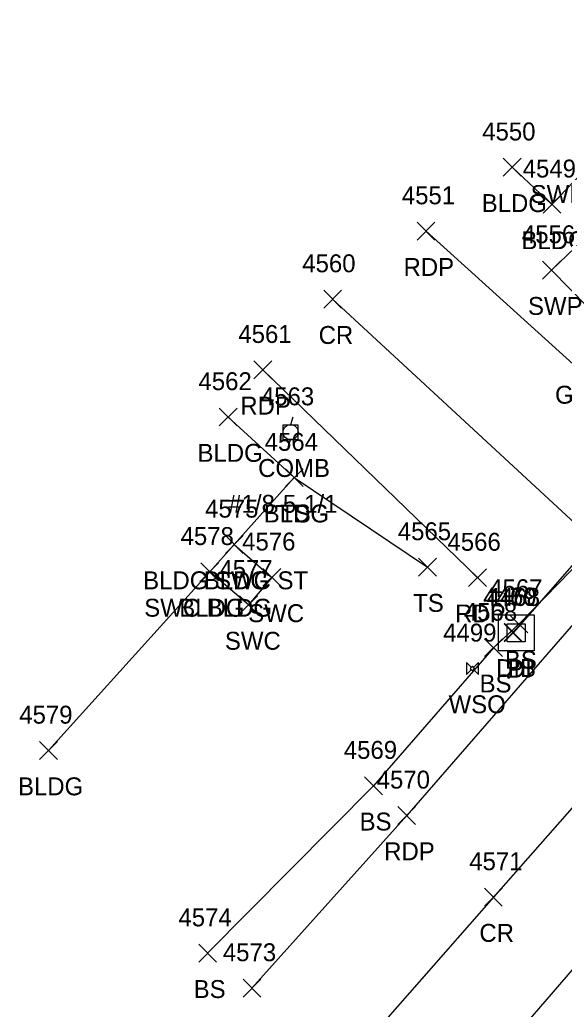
# Model space of a CAD drawing. Extents: x 1653135 to 1655489, y 602711 to 605684.
# Drawn here: x 1653134.6 to 1653195.4, y 604809.6 to 604920.1 of the extents above; entities that cross this region are included whole.
import ezdxf

# ---------------------------------------------------------------- set-up
doc = ezdxf.new("R2010")
doc.units = 0
for name, color, linetype in [('D_A', 7, 'Continuous'), ('D_I', 7, 'Continuous'), ('D_TIC', 7, 'Continuous'), ('DCP', 7, 'Continuous'), ('DS', 7, 'Continuous'), ('L_A', 7, 'Continuous'), ('L_I', 7, 'Continuous'), ('L_TIC', 7, 'Continuous'), ('LBC', 7, 'Continuous'), ('LELB', 7, 'Continuous'), ('P_A', 7, 'Continuous'), ('P_I', 7, 'Continuous'), ('P_TIC', 7, 'Continuous'), ('PET', 7, 'Continuous'), ('PRC', 7, 'Continuous'), ('R_A', 7, 'Continuous'), ('R_I', 7, 'Continuous'), ('R_TIC', 7, 'Continuous'), ('RSW', 7, 'Continuous'), ('S_C', 7, 'Continuous'), ('U_A', 7, 'Continuous'), ('U_C', 7, 'Continuous'), ('U_I', 7, 'Continuous'), ('UP', 7, 'Continuous'), ('UWV', 7, 'Continuous')]:
    doc.layers.add(name, color=color, linetype=linetype)

msp = doc.modelspace()

# ---------------------------------------------------------------- linework, layer by layer
at = {"layer": 'D_TIC'}
for points in [[(1653188.69, 604850.7), (1653190.69, 604852.7)], [(1653190.69, 604850.7), (1653188.69, 604852.7)], [(1653188.69, 604850.7), (1653190.69, 604852.7)], [(1653190.69, 604850.7), (1653188.69, 604852.7)], [(1653188.69, 604850.65), (1653190.69, 604852.65)], [(1653190.69, 604850.65), (1653188.69, 604852.65)], [(1653188.69, 604850.65), (1653190.69, 604852.65)], [(1653190.69, 604850.65), (1653188.69, 604852.65)]]:
    msp.add_lwpolyline(points, dxfattribs=at)
at = {"layer": 'DCP'}
msp.add_lwpolyline([(1653210.41, 604875.27), (1653189.69, 604851.65)], dxfattribs=at)
at = {"layer": 'DS'}
for p, q in [((1653188.05, 604853.64), (1653192.05, 604853.64)), ((1653188.05, 604849.64), (1653188.05, 604853.64)), ((1653189.05, 604850.64), (1653189.05, 604852.64)), ((1653189.05, 604852.64), (1653191.05, 604852.64)), ((1653191.05, 604852.64), (1653191.05, 604850.64)), ((1653192.05, 604853.64), (1653192.05, 604849.64)), ((1653190.06, 604851.64), (1653190.06, 604851.64)), ((1653190.06, 604851.64), (1653190.06, 604851.64)), ((1653191.05, 604850.64), (1653189.05, 604850.64)), ((1653192.05, 604849.64), (1653188.05, 604849.64))]:
    msp.add_line(p, q, dxfattribs=at)
at = {"layer": 'L_TIC'}
for points in [[(1653188.6, 604902.61), (1653190.6, 604904.61)], [(1653190.6, 604902.61), (1653188.6, 604904.61)], [(1653188.6, 604902.61), (1653190.6, 604904.61)], [(1653190.6, 604902.61), (1653188.6, 604904.61)], [(1653193.04, 604898.47), (1653195.04, 604900.47)], [(1653195.04, 604898.47), (1653193.04, 604900.47)], [(1653193.04, 604898.47), (1653195.04, 604900.47)], [(1653195.04, 604898.47), (1653193.04, 604900.47)], [(1653156.86, 604874.73), (1653158.86, 604876.73)], [(1653158.86, 604874.73), (1653156.86, 604876.73)], [(1653156.86, 604874.73), (1653158.86, 604876.73)], [(1653158.86, 604874.73), (1653156.86, 604876.73)], [(1653164.26, 604867.96), (1653166.26, 604869.96)], [(1653166.26, 604867.96), (1653164.26, 604869.96)], [(1653164.26, 604867.96), (1653166.26, 604869.96)], [(1653166.26, 604867.96), (1653164.26, 604869.96)], [(1653164.26, 604867.96), (1653166.26, 604869.96)], [(1653166.26, 604867.96), (1653164.26, 604869.96)], [(1653164.26, 604867.96), (1653166.26, 604869.96)], [(1653166.26, 604867.96), (1653164.26, 604869.96)], [(1653157.56, 604860.5), (1653159.56, 604862.5)], [(1653159.56, 604860.5), (1653157.56, 604862.5)], [(1653157.56, 604860.5), (1653159.56, 604862.5)], [(1653159.56, 604860.5), (1653157.56, 604862.5)], [(1653154.81, 604857.44), (1653156.81, 604859.44)], [(1653156.81, 604857.44), (1653154.81, 604859.44)], [(1653154.81, 604857.44), (1653156.81, 604859.44)], [(1653156.81, 604857.44), (1653154.81, 604859.44)], [(1653179.13, 604857.98), (1653181.13, 604859.98)], [(1653181.13, 604857.98), (1653179.13, 604859.98)], [(1653179.13, 604857.98), (1653181.13, 604859.98)], [(1653181.13, 604857.98), (1653179.13, 604859.98)], [(1653189.33, 604851.62), (1653191.33, 604853.62)], [(1653191.33, 604851.62), (1653189.33, 604853.62)], [(1653189.33, 604851.62), (1653191.33, 604853.62)], [(1653191.33, 604851.62), (1653189.33, 604853.62)], [(1653186.51, 604848.98), (1653188.51, 604850.98)], [(1653188.51, 604848.98), (1653186.51, 604850.98)], [(1653186.51, 604848.98), (1653188.51, 604850.98)], [(1653188.51, 604848.98), (1653186.51, 604850.98)], [(1653136.8, 604837.5), (1653138.8, 604839.5)], [(1653138.8, 604837.5), (1653136.8, 604839.5)], [(1653136.8, 604837.5), (1653138.8, 604839.5)], [(1653138.8, 604837.5), (1653136.8, 604839.5)], [(1653173.11, 604833.57), (1653175.11, 604835.57)], [(1653175.11, 604833.57), (1653173.11, 604835.57)], [(1653173.11, 604833.57), (1653175.11, 604835.57)], [(1653175.11, 604833.57), (1653173.11, 604835.57)], [(1653154.58, 604814.87), (1653156.58, 604816.87)], [(1653156.58, 604814.87), (1653154.58, 604816.87)], [(1653154.58, 604814.87), (1653156.58, 604816.87)], [(1653156.58, 604814.87), (1653154.58, 604816.87)]]:
    msp.add_lwpolyline(points, dxfattribs=at)
at = {"layer": 'LBC'}
for points in [[(1653219.99, 604933.48), (1653223.22, 604930.63), (1653221.42, 604928.5), (1653212.33, 604918.97), (1653207.68, 604913.99), (1653198.97, 604904.62), (1653194.04, 604899.47), (1653189.6, 604903.61)], [(1653157.86, 604875.73), (1653165.26, 604868.96), (1653158.56, 604861.5), (1653155.81, 604858.44), (1653137.8, 604838.5)]]:
    msp.add_lwpolyline(points, dxfattribs=at)
at = {"layer": 'LELB'}
for points in [[(1653208.32, 604875.11), (1653199.08, 604861.57), (1653190.33, 604852.62), (1653187.51, 604849.98), (1653174.11, 604834.57), (1653155.58, 604815.87)], [(1653165.26, 604868.96), (1653180.13, 604858.98)]]:
    msp.add_lwpolyline(points, dxfattribs=at)
at = {"layer": 'P_TIC'}
for points in [[(1653178.97, 604895.48), (1653180.97, 604897.48)], [(1653180.97, 604895.48), (1653178.97, 604897.48)], [(1653178.97, 604895.48), (1653180.97, 604897.48)], [(1653180.97, 604895.48), (1653178.97, 604897.48)], [(1653168.54, 604887.89), (1653170.54, 604889.89)], [(1653170.54, 604887.89), (1653168.54, 604889.89)], [(1653168.54, 604887.89), (1653170.54, 604889.89)], [(1653170.54, 604887.89), (1653168.54, 604889.89)], [(1653160.75, 604880), (1653162.75, 604882)], [(1653162.75, 604880), (1653160.75, 604882)], [(1653160.75, 604880), (1653162.75, 604882)], [(1653162.75, 604880), (1653160.75, 604882)], [(1653184.73, 604856.8), (1653186.73, 604858.8)], [(1653186.73, 604856.8), (1653184.73, 604858.8)], [(1653184.73, 604856.8), (1653186.73, 604858.8)], [(1653186.73, 604856.8), (1653184.73, 604858.8)], [(1653176.81, 604830.25), (1653178.81, 604832.25)], [(1653178.81, 604830.25), (1653176.81, 604832.25)], [(1653176.81, 604830.25), (1653178.81, 604832.25)], [(1653178.81, 604830.25), (1653176.81, 604832.25)], [(1653186.49, 604821.14), (1653188.49, 604823.14)], [(1653188.49, 604821.14), (1653186.49, 604823.14)], [(1653186.49, 604821.14), (1653188.49, 604823.14)], [(1653188.49, 604821.14), (1653186.49, 604823.14)], [(1653159.53, 604810.98), (1653161.53, 604812.98)], [(1653161.53, 604810.98), (1653159.53, 604812.98)], [(1653159.53, 604810.98), (1653161.53, 604812.98)], [(1653161.53, 604810.98), (1653159.53, 604812.98)]]:
    msp.add_lwpolyline(points, dxfattribs=at)
at = {"layer": 'PET'}
for points in [[(1653570.48, 605162.79), (1653545.4, 605152.19), (1653524.6, 605144.34), (1653501.66, 605134.24), (1653492.53, 605129.6), (1653483.22, 605126.16), (1653461.51, 605114.2), (1653431.75, 605097.05), (1653402.44, 605074.2), (1653383.5, 605058.49), (1653369.86, 605045.73), (1653350.11, 605021.59), (1653336.01, 605007.55), (1653322.85, 604993.82), (1653302.17, 604970.77), (1653290.93, 604958.38), (1653272.17, 604938.1), (1653250.65, 604913.14), (1653232.41, 604892.9), (1653208.36, 604866.32), (1653177.81, 604831.25), (1653160.53, 604811.98)], [(1653576.32, 605135.26), (1653553.77, 605126.84), (1653519.05, 605112.42), (1653493.54, 605100.34), (1653468.83, 605088), (1653447.85, 605075.02), (1653427.6, 605061.87), (1653406.78, 605044.61), (1653388.9, 605027.7), (1653366.5, 605004.89), (1653354.58, 604992.02), (1653334.9, 604970.66), (1653318.05, 604952.19), (1653296.49, 604928.19), (1653274.62, 604903.56), (1653244.24, 604868.76), (1653225.75, 604847.7), (1653206.33, 604825.65), (1653179.65, 604794.75)], [(1653179.97, 604896.48), (1653201.88, 604876.69)], [(1653161.75, 604881), (1653185.73, 604857.8)]]:
    msp.add_lwpolyline(points, dxfattribs=at)
at = {"layer": 'PRC'}
for points in [[(1653576.36, 605149.52), (1653550.32, 605139.02), (1653518.72, 605125.67), (1653498.02, 605116.67), (1653468.04, 605101.49), (1653440.12, 605084.85), (1653411.97, 605063.45), (1653392.18, 605045.92), (1653380.93, 605035.31), (1653360.25, 605013.97), (1653332.49, 604984.79), (1653311.15, 604961.54), (1653300.12, 604949.23), (1653281.61, 604928.68), (1653260.96, 604905.28), (1653242.09, 604884.43), (1653216.57, 604855.12), (1653187.49, 604822.14), (1653170.08, 604802.31)], [(1653199.08, 604861.57), (1653169.54, 604888.89)]]:
    msp.add_lwpolyline(points, dxfattribs=at)
at = {"layer": 'R_TIC'}
for points in [[(1653192.99, 604891.13), (1653194.99, 604893.13)], [(1653194.99, 604891.13), (1653192.99, 604893.13)], [(1653192.99, 604891.13), (1653194.99, 604893.13)], [(1653194.99, 604891.13), (1653192.99, 604893.13)], [(1653157.56, 604860.5), (1653159.56, 604862.5)], [(1653159.56, 604860.5), (1653157.56, 604862.5)], [(1653157.56, 604860.5), (1653159.56, 604862.5)], [(1653159.56, 604860.5), (1653157.56, 604862.5)], [(1653154.81, 604857.44), (1653156.81, 604859.44)], [(1653156.81, 604857.44), (1653154.81, 604859.44)], [(1653154.81, 604857.44), (1653156.81, 604859.44)], [(1653156.81, 604857.44), (1653154.81, 604859.44)], [(1653161.75, 604856.83), (1653163.75, 604858.83)], [(1653163.75, 604856.83), (1653161.75, 604858.83)], [(1653161.75, 604856.83), (1653163.75, 604858.83)], [(1653163.75, 604856.83), (1653161.75, 604858.83)], [(1653159.15, 604853.75), (1653161.15, 604855.75)], [(1653161.15, 604853.75), (1653159.15, 604855.75)], [(1653159.15, 604853.75), (1653161.15, 604855.75)], [(1653161.15, 604853.75), (1653159.15, 604855.75)]]:
    msp.add_lwpolyline(points, dxfattribs=at)
at = {"layer": 'RSW'}
for points in [[(1653211.16, 604886.92), (1653204.07, 604892.89), (1653199.17, 604897.08), (1653193.99, 604892.13), (1653204.08, 604881.84)], [(1653158.56, 604861.5), (1653162.75, 604857.83), (1653160.15, 604854.75), (1653155.81, 604858.44)]]:
    msp.add_lwpolyline(points, dxfattribs=at)
at = {"layer": 'UP'}
for p, q in [((1653164, 604873.2), (1653164, 604874.87)), ((1653164, 604874.87), (1653165.67, 604874.87)), ((1653165.09, 604875.7), (1653164.84, 604874.87)), ((1653165.67, 604874.87), (1653165.67, 604873.2)), ((1653164.84, 604874.04), (1653164.84, 604874.04)), ((1653165.67, 604873.2), (1653164, 604873.2)), ((1653164.59, 604872.37), (1653164.84, 604873.2))]:
    msp.add_line(p, q, dxfattribs=at)
msp.add_circle((1653164.84, 604874.04), 0.833, dxfattribs=at)
at = {"layer": 'UWV'}
for p, q in [((1653184.49, 604848.33), (1653185.04, 604847.78)), ((1653185.82, 604848.33), (1653185.27, 604847.78)), ((1653185.04, 604847.54), (1653184.49, 604846.99)), ((1653185.27, 604847.54), (1653185.82, 604846.99))]:
    msp.add_line(p, q, dxfattribs=at)
for points in [[(1653184.49, 604848.33), (1653184.49, 604846.99)], [(1653185.82, 604846.99), (1653185.82, 604848.33)]]:
    msp.add_lwpolyline(points, dxfattribs=at)
msp.add_lwpolyline([(1653185.39, 604847.66), (1653185.16, 604847.9), (1653184.92, 604847.66), (1653185.16, 604847.43)], close=True, dxfattribs=at)

# ---------------------------------------------------------------- texts
at = {"layer": 'D_A'}
for s, p in [('DIB', (1653187.79, 604846.7)), ('DIB', (1653187.79, 604846.7)), ('P', (1653189.07, 604846.65)), ('P', (1653189.07, 604846.65)), ('DI', (1653189.11, 604846.64))]:
    msp.add_text(s, height=2, dxfattribs=at).set_placement(p)
at = {"layer": 'D_I'}
for s, p in [('4470', (1653186.34, 604854.65)), ('4470', (1653186.34, 604854.65)), ('4469', (1653186.37, 604854.7)), ('4469', (1653186.37, 604854.7)), ('4468', (1653186.75, 604854.64))]:
    msp.add_text(s, height=2, dxfattribs=at).set_placement(p)
at = {"layer": 'L_A'}
for s, p in [('BLDG', (1653186.19, 604898.61)), ('BLDG', (1653186.19, 604898.61)), ('BLDG', (1653190.63, 604894.47)), ('BLDG', (1653190.63, 604894.47)), ('BLDG', (1653154.45, 604870.73)), ('BLDG', (1653154.45, 604870.73)), ('BLDG', (1653161.85, 604863.96)), ('BLDG', (1653161.85, 604863.96)), ('TS', (1653163.67, 604863.96)), ('TS', (1653163.67, 604863.96)), ('BLDG', (1653155.15, 604856.5)), ('BLDG', (1653155.15, 604856.5)), ('TS', (1653178.54, 604853.98)), ('TS', (1653178.54, 604853.98)), ('BLDG', (1653152.41, 604853.44)), ('BLDG', (1653152.41, 604853.44)), ('BS', (1653188.78, 604847.62)), ('BS', (1653188.78, 604847.62)), ('BS', (1653185.95, 604844.98)), ('BS', (1653185.95, 604844.98)), ('BLDG', (1653134.4, 604833.5)), ('BLDG', (1653134.4, 604833.5)), ('BS', (1653172.55, 604829.57)), ('BS', (1653172.55, 604829.57)), ('BS', (1653154.02, 604810.87)), ('BS', (1653154.02, 604810.87))]:
    msp.add_text(s, height=2, dxfattribs=at).set_placement(p)
at = {"layer": 'L_I'}
for s, p in [('4550', (1653186.25, 604906.61)), ('4550', (1653186.25, 604906.61)), ('4549', (1653190.77, 604902.47)), ('4549', (1653190.77, 604902.47)), ('4562', (1653154.56, 604878.73)), ('4562', (1653154.56, 604878.73)), ('4564', (1653161.95, 604871.96)), ('4564', (1653161.95, 604871.96)), ('4564', (1653161.95, 604871.96)), ('4564', (1653161.95, 604871.96)), ('4575', (1653155.3, 604864.5)), ('4575', (1653155.3, 604864.5)), ('4565', (1653176.82, 604861.98)), ('4565', (1653176.82, 604861.98)), ('4578', (1653152.56, 604861.44)), ('4578', (1653152.56, 604861.44)), ('4567', (1653187.03, 604855.62)), ('4567', (1653187.03, 604855.62)), ('4568', (1653184.2, 604852.98)), ('4568', (1653184.2, 604852.98)), ('4579', (1653134.54, 604841.5)), ('4579', (1653134.54, 604841.5)), ('4569', (1653170.79, 604837.57)), ('4569', (1653170.79, 604837.57)), ('4574', (1653152.32, 604818.87)), ('4574', (1653152.32, 604818.87))]:
    msp.add_text(s, height=2, dxfattribs=at).set_placement(p)
at = {"layer": 'P_A'}
for s, p in [('RDP', (1653177.46, 604891.48)), ('RDP', (1653177.46, 604891.48)), ('CR', (1653167.98, 604883.89)), ('CR', (1653167.98, 604883.89)), ('RDP', (1653159.23, 604876)), ('RDP', (1653159.23, 604876)), ('RDP', (1653183.22, 604852.8)), ('RDP', (1653183.22, 604852.8)), ('RDP', (1653175.3, 604826.25)), ('RDP', (1653175.3, 604826.25)), ('CR', (1653185.93, 604817.14)), ('CR', (1653185.93, 604817.14))]:
    msp.add_text(s, height=2, dxfattribs=at).set_placement(p)
at = {"layer": 'P_I'}
for s, p in [('4551', (1653177.27, 604899.48)), ('4551', (1653177.27, 604899.48)), ('4560', (1653166.15, 604891.89)), ('4560', (1653166.15, 604891.89)), ('4561', (1653159.01, 604884)), ('4561', (1653159.01, 604884)), ('4566', (1653182.37, 604860.8)), ('4566', (1653182.37, 604860.8)), ('4570', (1653174.46, 604834.25)), ('4570', (1653174.46, 604834.25)), ('4571', (1653184.8, 604825.14)), ('4571', (1653184.8, 604825.14)), ('4573', (1653157.28, 604814.98)), ('4573', (1653157.28, 604814.98))]:
    msp.add_text(s, height=2, dxfattribs=at).set_placement(p)
at = {"layer": 'R_A'}
for s, p in [('SWP BLDG', (1653191.66, 604899.62)), ('SWP BLDG', (1653191.66, 604899.62)), ('SWP', (1653191.36, 604887.13)), ('SWP', (1653191.36, 604887.13)), ('BLDG SWC ST', (1653148.38, 604856.5)), ('BLDG SWC ST', (1653148.38, 604856.5)), ('SWC BLDG', (1653148.5, 604853.44)), ('SWC BLDG', (1653148.5, 604853.44)), ('SWC', (1653160.12, 604852.83)), ('SWC', (1653160.12, 604852.83)), ('SWC', (1653157.51, 604849.75)), ('SWC', (1653157.51, 604849.75))]:
    msp.add_text(s, height=2, dxfattribs=at).set_placement(p)
at = {"layer": 'R_I'}
for s, p in [('4556', (1653190.68, 604895.13)), ('4556', (1653190.68, 604895.13)), ('4575', (1653155.3, 604864.5)), ('4575', (1653155.3, 604864.5)), ('4578', (1653152.56, 604861.44)), ('4578', (1653152.56, 604861.44)), ('4576', (1653159.44, 604860.83)), ('4576', (1653159.44, 604860.83)), ('4577', (1653156.89, 604857.75)), ('4577', (1653156.89, 604857.75))]:
    msp.add_text(s, height=2, dxfattribs=at).set_placement(p)
at = {"layer": 'S_C'}
msp.add_text('GARDEN ST', height=2, dxfattribs=at).set_placement((1653194.38, 604877.22))
at = {"layer": 'U_A'}
for s, p in [('COMB', (1653161.22, 604869.04)), ('WSO', (1653182.49, 604842.66))]:
    msp.add_text(s, height=2, dxfattribs=at).set_placement(p)
at = {"layer": 'U_C'}
msp.add_text('#1/8-5-1/1', height=2, dxfattribs=at).set_placement((1653157.89, 604865.04))
at = {"layer": 'U_I'}
for s, p in [('4563', (1653161.53, 604877.04)), ('4499', (1653181.89, 604850.66))]:
    msp.add_text(s, height=2, dxfattribs=at).set_placement(p)

doc.saveas('drawing.dxf')
